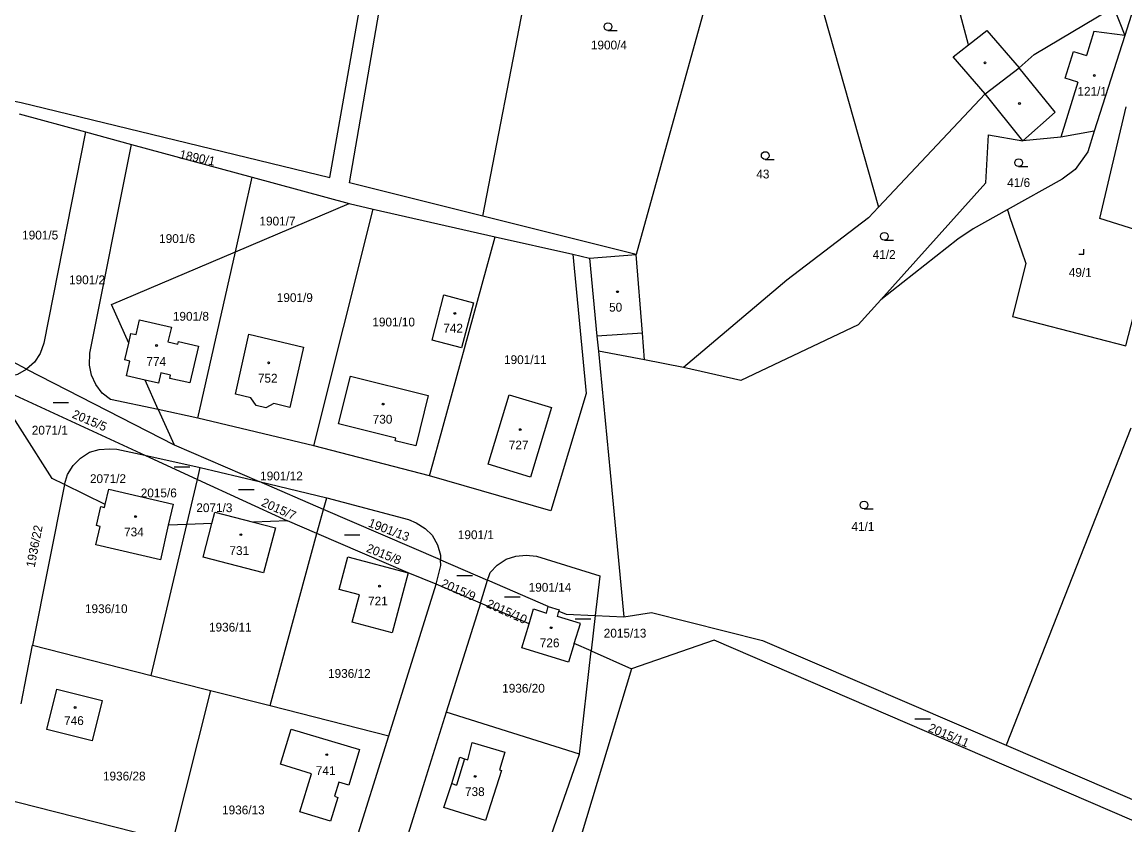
# Model space of a CAD drawing. Extents: x -794765 to -785424, y -1118958 to -1108731.
# Drawn here: x -788490.9 to -788278.3, y -1116664.5 to -1116509.6 of the extents above; entities that cross this region are included whole.
import ezdxf

# ---------------------------------------------------------------- set-up
doc = ezdxf.new("R2010")
doc.units = 0
for name, color, linetype in [('Level 66', 7, 'Continuous'), ('Level 75', 7, 'Continuous'), ('Level 76', 7, 'Continuous'), ('Level 77', 7, 'Continuous'), ('Level 79', 7, 'Continuous')]:
    doc.layers.add(name, color=color, linetype=linetype)

msp = doc.modelspace()

# ---------------------------------------------------------------- linework, layer by layer
at = {"layer": 'Level 66'}
for p, q in [((-788377.99, -1116511.28), (-788376.24, -1116511.28)), ((-788347.67, -1116536.14), (-788345.92, -1116536.14)), ((-788298.82, -1116537.52), (-788297.07, -1116537.52)), ((-788324.7, -1116551.71), (-788322.95, -1116551.71)), ((-788286.23, -1116554.42), (-788286.23, -1116553.42)), ((-788287.23, -1116554.42), (-788286.23, -1116554.42)), ((-788484.97, -1116583), (-788481.97, -1116583)), ((-788461.61, -1116595.4), (-788458.61, -1116595.4)), ((-788449.18, -1116599.76), (-788446.18, -1116599.76)), ((-788328.62, -1116603.54), (-788326.87, -1116603.54)), ((-788428.79, -1116608.55), (-788425.79, -1116608.55)), ((-788407.1, -1116616.4), (-788404.1, -1116616.4)), ((-788397.9, -1116620.47), (-788394.9, -1116620.47)), ((-788384.3, -1116624.72), (-788381.3, -1116624.72)), ((-788318.8, -1116644.03), (-788315.8, -1116644.03))]:
    msp.add_line(p, q, dxfattribs=at)
for centre in [(-788377.99, -1116510.53), (-788347.67, -1116535.39), (-788298.82, -1116536.77), (-788324.7, -1116550.96), (-788328.62, -1116602.79)]:
    msp.add_circle(centre, 0.75, dxfattribs=at)
at = {"layer": 'Level 75'}
for p, q in [((-788402.13, -1116547.05), (-788387.31, -1116470.88)), ((-788355.49, -1116492.94), (-788372.54, -1116554.44)), ((-788338.01, -1116502.23), (-788325.84, -1116545.35)), ((-788280.56, -1116506.71), (-788278.35, -1116512.25)), ((-788278.35, -1116512.25), (-788284.27, -1116530.68)), ((-788305.27, -1116523.5), (-788325.84, -1116545.35)), ((-788297.98, -1116532.55), (-788305.27, -1116523.5)), ((-788491.48, -1116527.33), (-788478.73, -1116530.8)), ((-788478.73, -1116530.8), (-788469.84, -1116533.23)), ((-788469.84, -1116533.23), (-788446.58, -1116539.57)), ((-788449.82, -1116553.98), (-788446.58, -1116539.57)), ((-788446.58, -1116539.57), (-788427.9, -1116544.66)), ((-788290.41, -1116539.96), (-788301, -1116545.84)), ((-788449.82, -1116553.98), (-788427.9, -1116544.66)), ((-788427.9, -1116544.66), (-788423.28, -1116545.71)), ((-788434.66, -1116591.36), (-788423.28, -1116545.71)), ((-788423.28, -1116545.71), (-788399.74, -1116551.03)), ((-788372.54, -1116554.44), (-788402.13, -1116547.05)), ((-788301, -1116545.84), (-788307.59, -1116549.5)), ((-788307.59, -1116549.5), (-788310.51, -1116551.48)), ((-788399.74, -1116551.03), (-788384.76, -1116554.42)), ((-788310.51, -1116551.48), (-788325.4, -1116563.23)), ((-788457.04, -1116586.01), (-788449.82, -1116553.98)), ((-788384.76, -1116554.42), (-788381.52, -1116555.15)), ((-788381.52, -1116555.15), (-788372.54, -1116554.44)), ((-788470.37, -1116571.57), (-788469.94, -1116569.69)), ((-788471.11, -1116574.8), (-788470.37, -1116571.57)), ((-788370.92, -1116574.81), (-788379.78, -1116573.09)), ((-788363.45, -1116576.26), (-788370.92, -1116574.81)), ((-788490.08, -1116576.56), (-788492.74, -1116575.19)), ((-788490.08, -1116576.56), (-788461.64, -1116591.17)), ((-788467.2, -1116578.68), (-788470.78, -1116577.86)), ((-788464.67, -1116584.38), (-788467.2, -1116578.68)), ((-788464.65, -1116579.27), (-788467.2, -1116578.68)), ((-788496.63, -1116579.65), (-788467.26, -1116593.19)), ((-788457.04, -1116586.01), (-788464.67, -1116584.38)), ((-788464.67, -1116584.38), (-788461.64, -1116591.17)), ((-788434.66, -1116591.36), (-788457.04, -1116586.01)), ((-788277.22, -1116587.97), (-788301.21, -1116649.08)), ((-788461.64, -1116591.17), (-788445.21, -1116598.27)), ((-788412.36, -1116597.13), (-788434.66, -1116591.36)), ((-788467.26, -1116593.19), (-788456.58, -1116595.52)), ((-788467.26, -1116593.19), (-788457.13, -1116597.86)), ((-788457.13, -1116597.86), (-788456.58, -1116595.52)), ((-788456.58, -1116595.52), (-788445.21, -1116598.27)), ((-788459.18, -1116606.54), (-788457.13, -1116597.86)), ((-788457.13, -1116597.86), (-788439.79, -1116605.86)), ((-788445.21, -1116598.27), (-788432.2, -1116601.41)), ((-788432.81, -1116603.63), (-788445.21, -1116598.27)), ((-788482.78, -1116598.82), (-788488.9, -1116629.83)), ((-788474.89, -1116602.67), (-788482.78, -1116598.82)), ((-788474.89, -1116602.67), (-788474.22, -1116599.75)), ((-788474.22, -1116599.75), (-788461.82, -1116602.62)), ((-788475.02, -1116603.25), (-788474.89, -1116602.67)), ((-788461.82, -1116602.62), (-788462.75, -1116606.67)), ((-788432.81, -1116603.63), (-788432.2, -1116601.41)), ((-788434.08, -1116608.29), (-788432.81, -1116603.63)), ((-788410.24, -1116613.38), (-788432.81, -1116603.63)), ((-788466.02, -1116635.65), (-788459.18, -1116606.54)), ((-788462.75, -1116606.67), (-788464.27, -1116613.33)), ((-788459.18, -1116606.54), (-788462.75, -1116606.67)), ((-788454.34, -1116606.37), (-788459.18, -1116606.54)), ((-788439.79, -1116605.86), (-788446.34, -1116606.09)), ((-788434.08, -1116608.29), (-788439.79, -1116605.86)), ((-788443.12, -1116641.46), (-788434.08, -1116608.29)), ((-788410.24, -1116613.38), (-788401.19, -1116617.29)), ((-788402.57, -1116621.69), (-788401.19, -1116617.29)), ((-788389.49, -1116622.34), (-788401.19, -1116617.29)), ((-788379.57, -1116616.52), (-788380.44, -1116624.08)), ((-788420.23, -1116647.28), (-788411.08, -1116618.07)), ((-788402.57, -1116621.69), (-788411.08, -1116618.07)), ((-788402.57, -1116621.69), (-788409.17, -1116642.74)), ((-788393.2, -1116625.68), (-788402.57, -1116621.69)), ((-788380.44, -1116624.08), (-788381.23, -1116630.92)), ((-788380.44, -1116624.08), (-788374.9, -1116624.32)), ((-788491.13, -1116641.15), (-788488.9, -1116629.83)), ((-788488.9, -1116629.83), (-788466.02, -1116635.65)), ((-788381.23, -1116630.92), (-788384.47, -1116629.47)), ((-788383.5, -1116650.8), (-788381.23, -1116630.92)), ((-788381.23, -1116630.92), (-788373.45, -1116634.4)), ((-788373.45, -1116634.4), (-788420.97, -1116791.2)), ((-788466.02, -1116635.65), (-788454.6, -1116638.55)), ((-788454.6, -1116638.55), (-788461.96, -1116667.65)), ((-788454.6, -1116638.55), (-788443.12, -1116641.46)), ((-788443.12, -1116641.46), (-788420.23, -1116647.28)), ((-788409.17, -1116642.74), (-788413.34, -1116656.08)), ((-788383.5, -1116650.8), (-788409.17, -1116642.74)), ((-788429.2, -1116676), (-788420.23, -1116647.28)), ((-788394.62, -1116682.97), (-788383.5, -1116650.8)), ((-788413.34, -1116656.08), (-788419.35, -1116675.22)), ((-788495.6, -1116659.1), (-788461.96, -1116667.65))]:
    msp.add_line(p, q, dxfattribs=at)
for points in [[(-788614.4, -1116497.78), (-788554.99, -1116511.96), (-788491.11, -1116525.14), (-788431.6, -1116539.59), (-788422.48, -1116487.78), (-788421.23, -1116481.16)], [(-788402.13, -1116547.05), (-788427.84, -1116540.63), (-788417.94, -1116483.29), (-788417.71, -1116481.98)], [(-788305.27, -1116523.5), (-788311.46, -1116516.37), (-788308.5, -1116514.03), (-788310.02, -1116508.25), (-788301.03, -1116503.62), (-788296.47, -1116500.79), (-788282.91, -1116496.51)], [(-788305.27, -1116523.5), (-788298.71, -1116518.45), (-788295.85, -1116515.9), (-788281.22, -1116507.22), (-788280.56, -1116506.71)], [(-788272.23, -1116508.1), (-788276.71, -1116507.17), (-788278.35, -1116512.25)], [(-788268.24, -1116552.2), (-788283.18, -1116547.55), (-788278.12, -1116526)], [(-788478.73, -1116530.8), (-788486.77, -1116571.58), (-788487.43, -1116573.53), (-788488.51, -1116575.22), (-788490.08, -1116576.56)], [(-788325.4, -1116563.23), (-788305.13, -1116540.66), (-788304.64, -1116531.4), (-788297.98, -1116532.55)], [(-788284.27, -1116530.68), (-788290.69, -1116531.87), (-788297.98, -1116532.55)], [(-788284.27, -1116530.68), (-788285.48, -1116534.65), (-788287.95, -1116538.05), (-788290.41, -1116539.96)], [(-788464.67, -1116584.38), (-788473.88, -1116582.41), (-788475.48, -1116581.2), (-788476.71, -1116579.54), (-788477.56, -1116577.77), (-788477.94, -1116575.8), (-788477.84, -1116573.5), (-788469.84, -1116533.23)], [(-788325.84, -1116545.35), (-788327.76, -1116547.39), (-788343.5, -1116559.45), (-788363.45, -1116576.26)], [(-788301, -1116545.84), (-788300.92, -1116546.07), (-788300.42, -1116547.52), (-788298.26, -1116553.75), (-788297.42, -1116556.2), (-788299.98, -1116566.4), (-788278.14, -1116572.05), (-788275.49, -1116561.89), (-788271.12, -1116563.8)], [(-788412.36, -1116597.13), (-788412.24, -1116596.7), (-788399.74, -1116551.03)], [(-788470.37, -1116571.57), (-788473.68, -1116564.13), (-788449.82, -1116553.98)], [(-788384.76, -1116554.42), (-788382.22, -1116581.27), (-788388.99, -1116603.9), (-788412.36, -1116597.13)], [(-788381.52, -1116555.15), (-788380.15, -1116570.22), (-788379.78, -1116573.09)], [(-788370.92, -1116574.81), (-788371.33, -1116569.66), (-788372.54, -1116554.44)], [(-788411.9, -1116570.96), (-788409.6, -1116562.26), (-788403.89, -1116563.78), (-788406.2, -1116572.49), (-788411.9, -1116570.96)], [(-788325.4, -1116563.23), (-788329.74, -1116568.06), (-788352.38, -1116578.79), (-788363.45, -1116576.26)], [(-788469.94, -1116569.69), (-788468.96, -1116569.91), (-788468.3, -1116567.07), (-788462.15, -1116568.49), (-788462.81, -1116571.32), (-788460.92, -1116571.76), (-788460.8, -1116571.24), (-788456.93, -1116572.13), (-788458.57, -1116579.24), (-788462.43, -1116578.35), (-788462.29, -1116577.76), (-788464.19, -1116577.32), (-788464.65, -1116579.27)], [(-788442.4, -1116583.2), (-788443.94, -1116584.07), (-788445.82, -1116583.61), (-788446.81, -1116582.13), (-788449.81, -1116581.39), (-788447.19, -1116569.82), (-788436.65, -1116572.36), (-788439.34, -1116583.96), (-788442.4, -1116583.2)], [(-788470.78, -1116577.86), (-788470.15, -1116575.03), (-788471.11, -1116574.8)], [(-788379.78, -1116573.09), (-788377.55, -1116596.5), (-788374.9, -1116624.32)], [(-788500.6, -1116576.98), (-788496.27, -1116577.93), (-788493.73, -1116577.98), (-788491.73, -1116577.56), (-788490.08, -1116576.56)], [(-788412.63, -1116581.69), (-788415.05, -1116591.37), (-788418.98, -1116590.42), (-788418.85, -1116589.91), (-788429.95, -1116587.14), (-788427.64, -1116577.93), (-788412.63, -1116581.69)], [(-788482.78, -1116598.82), (-788485.13, -1116597.68), (-788496.63, -1116579.65)], [(-788392.93, -1116597.38), (-788401.09, -1116594.91), (-788397.03, -1116581.5), (-788388.88, -1116583.96), (-788392.93, -1116597.38)], [(-788482.78, -1116598.82), (-788482.17, -1116596.88), (-788481.1, -1116595.16), (-788479.69, -1116593.75), (-788477.96, -1116592.61), (-788476.08, -1116592.08), (-788474.08, -1116591.93), (-788472.68, -1116592.01), (-788467.26, -1116593.19)], [(-788432.2, -1116601.41), (-788416.41, -1116605.58), (-788414.93, -1116606.22), (-788413.25, -1116607.31), (-788411.87, -1116608.62), (-788410.86, -1116610.49), (-788410.29, -1116612.42), (-788410.24, -1116613.38)], [(-788464.27, -1116613.33), (-788476.69, -1116610.46), (-788475.86, -1116606.94), (-788476.61, -1116606.76), (-788475.75, -1116603.08), (-788475.02, -1116603.25)], [(-788454.34, -1116606.37), (-788453.76, -1116604.15), (-788446.34, -1116606.09)], [(-788446.34, -1116606.09), (-788442.11, -1116607.2), (-788444.37, -1116615.89), (-788456.02, -1116612.86), (-788454.34, -1116606.37)], [(-788411.08, -1116618.07), (-788416.52, -1116615.83), (-788434.08, -1116608.29)], [(-788416.52, -1116615.83), (-788419.57, -1116627.43), (-788427.33, -1116625.36), (-788425.9, -1116620.07), (-788429.78, -1116619.05), (-788428.11, -1116612.77), (-788416.52, -1116615.83)], [(-788411.08, -1116618.07), (-788410.18, -1116614.42), (-788410.24, -1116613.38)], [(-788401.19, -1116617.29), (-788400.85, -1116616.17), (-788400.72, -1116615.8), (-788399.33, -1116614.36), (-788397.6, -1116613.21), (-788395.73, -1116612.63), (-788393.73, -1116612.44), (-788391.75, -1116612.66), (-788379.57, -1116616.41), (-788379.57, -1116616.52)], [(-788393.2, -1116625.68), (-788392.34, -1116622.83), (-788389.84, -1116623.61), (-788389.49, -1116622.34)], [(-788389.49, -1116622.34), (-788387.39, -1116623), (-788387.45, -1116623.22)], [(-788384.47, -1116629.47), (-788383.3, -1116625.61), (-788387.74, -1116624.25), (-788387.45, -1116623.22)], [(-788387.45, -1116623.22), (-788386.05, -1116623.83), (-788380.44, -1116624.08)], [(-788374.9, -1116624.32), (-788369.6, -1116623.49), (-788348.19, -1116628.91), (-788301.21, -1116649.08)], [(-788384.47, -1116629.47), (-788385.57, -1116633.1), (-788394.62, -1116630.31), (-788393.2, -1116625.68)], [(-788266.33, -1116668.19), (-788268.66, -1116667.18), (-788301.6, -1116652.96), (-788357.49, -1116628.83), (-788373.45, -1116634.4)], [(-788477.45, -1116648.28), (-788486.16, -1116646.06), (-788484.21, -1116638.29), (-788475.47, -1116640.51), (-788477.45, -1116648.28)], [(-788439.05, -1116645.98), (-788425.86, -1116649.96), (-788427.95, -1116656.78), (-788429.87, -1116656.22), (-788430.71, -1116658.95), (-788430.04, -1116659.16), (-788431.46, -1116663.74), (-788437.38, -1116661.92), (-788435.12, -1116654.61), (-788441.14, -1116652.76), (-788439.05, -1116645.98)], [(-788405.03, -1116651.91), (-788404.17, -1116648.6), (-788397.87, -1116650.44), (-788398.88, -1116653.84), (-788398.5, -1116653.96), (-788401.58, -1116663.64), (-788409.65, -1116661.12), (-788408.1, -1116656.46), (-788406.56, -1116651.42), (-788405.62, -1116651.72), (-788405.03, -1116651.91)], [(-788301.21, -1116649.08), (-788267.3, -1116663.67), (-788264.77, -1116664.43)]]:
    msp.add_lwpolyline(points, dxfattribs=at)
at = {"layer": 'Level 77'}
for p, q in [((-788308.5, -1116514.03), (-788304.98, -1116511.24)), ((-788304.98, -1116511.24), (-788298.71, -1116518.45)), ((-788284.29, -1116511.44), (-788285.75, -1116516.09)), ((-788278.35, -1116512.25), (-788284.29, -1116511.44)), ((-788289.83, -1116520.46), (-788288.25, -1116515.35)), ((-788288.25, -1116515.35), (-788285.75, -1116516.09)), ((-788291.8, -1116527.01), (-788298.71, -1116518.45)), ((-788287.38, -1116521.26), (-788290.69, -1116531.87)), ((-788287.38, -1116521.26), (-788289.83, -1116520.46)), ((-788297.98, -1116532.55), (-788291.8, -1116527.01)), ((-788371.33, -1116569.66), (-788380.15, -1116570.22)), ((-788405.62, -1116651.72), (-788407.19, -1116656.78)), ((-788408.1, -1116656.46), (-788407.19, -1116656.78))]:
    msp.add_line(p, q, dxfattribs=at)
at = {"layer": 'Level 79'}
for centre in [(-788305.3, -1116517.51), (-788284.23, -1116519.94), (-788298.66, -1116525.34), (-788376.15, -1116561.65), (-788407.51, -1116565.82), (-788465, -1116572.03), (-788443.4, -1116575.35), (-788421.31, -1116583.31), (-788394.89, -1116588.24), (-788469.05, -1116605.01), (-788448.74, -1116608.5), (-788422.01, -1116618.43), (-788388.93, -1116626.45), (-788480.72, -1116641.82), (-788432.2, -1116650.93), (-788403.59, -1116655.11)]:
    msp.add_circle(centre, 0.175, dxfattribs=at)

# ---------------------------------------------------------------- texts
at = {"layer": 'Level 76'}
for s, p in [('1900/4', (-788381.28, -1116514.92)), ('121/1', (-788287.48, -1116523.85)), ('43', (-788349.39, -1116539.8)), ('41/6', (-788301.03, -1116541.45)), ('1901/7', (-788445.17, -1116548.87)), ('1901/5', (-788490.92, -1116551.57)), ('1901/6', (-788464.51, -1116552.25)), ('41/2', (-788326.95, -1116555.32)), ('49/1', (-788289.15, -1116558.77)), ('1901/2', (-788481.88, -1116560.2)), ('1901/9', (-788441.83, -1116563.64)), ('50', (-788377.77, -1116565.49)), ('1901/8', (-788461.86, -1116567.24)), ('1901/10', (-788423.41, -1116568.34)), ('742', (-788409.73, -1116569.53)), ('774', (-788466.96, -1116575.95)), ('1901/11', (-788398.02, -1116575.6)), ('752', (-788445.47, -1116579.18)), ('730', (-788423.34, -1116587.09)), ('2071/1', (-788489.06, -1116589.2)), ('727', (-788397.1, -1116592.06)), ('1901/12', (-788445.04, -1116598.03)), ('2071/2', (-788477.85, -1116598.55)), ('2015/6', (-788468.06, -1116601.3)), ('2071/3', (-788457.34, -1116604.15)), ('41/1', (-788331.05, -1116607.77)), ('734', (-788471.27, -1116608.83)), ('1901/1', (-788406.93, -1116609.36)), ('731', (-788450.96, -1116612.42)), ('1901/14', (-788393.27, -1116619.5)), ('1936/10', (-788478.81, -1116623.63)), ('721', (-788424.23, -1116622.15)), ('1936/11', (-788454.9, -1116627.19)), ('2015/13', (-788378.8, -1116628.34)), ('726', (-788391.13, -1116630.22)), ('1936/12', (-788431.95, -1116636.11)), ('1936/20', (-788398.38, -1116638.97)), ('746', (-788482.83, -1116645.21)), ('741', (-788434.3, -1116654.85)), ('1936/28', (-788475.34, -1116655.9)), ('738', (-788405.55, -1116658.91)), ('1936/13', (-788452.38, -1116662.44))]:
    msp.add_text(s, height=1.7, dxfattribs=at).set_placement(p)
for s, rotation, p in [('1890/1', 348, (-788460.71, -1116535.92)), ('2015/5', 337, (-788481.43, -1116585.89)), ('2015/7', 336, (-788444.95, -1116602.89)), ('1936/22', 79, (-788488.52, -1116614.91)), ('1901/13', 339, (-788424.35, -1116606.88)), ('2015/8', 338, (-788424.72, -1116611.74)), ('2015/9', 336, (-788410.33, -1116618.49)), ('2015/10', 336, (-788401.57, -1116622.42)), ('2015/11', 337, (-788316.38, -1116646.36))]:
    msp.add_text(s, height=1.7, rotation=rotation, dxfattribs=at).set_placement(p)

doc.saveas('drawing.dxf')
